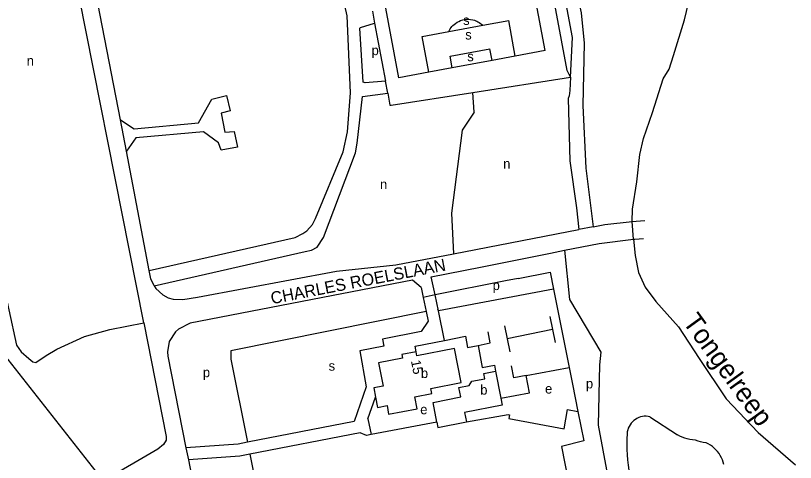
# Model space of a CAD drawing. Extents: x 160204 to 161526, y 379528 to 381793.
# Drawn here: x 160863 to 161185.5, y 379877.4 to 380062.1 of the extents above; entities that cross this region are included whole.
import ezdxf

# ---------------------------------------------------------------- set-up
doc = ezdxf.new("R2010")
doc.units = 0
for name, color, linetype in [('BLT_Basislijn', 7, 'Continuous'), ('BLT_Bebouwing', 7, 'Continuous'), ('BLT_Centroide', 7, 'Continuous'), ('BLT_Huisnummer', 7, 'Continuous'), ('BLT_Straatnaam', 7, 'Continuous'), ('BLT_Vlakafsluiter', 7, 'Continuous'), ('BLT_Waternaam_spoorwegen', 7, 'Continuous')]:
    doc.layers.add(name, color=color, linetype=linetype)

msp = doc.modelspace()

# ---------------------------------------------------------------- linework, layer by layer
at = {"layer": 'BLT_Basislijn'}
for p, q in [((161081.96, 380047.64), (161073.27, 380094.34)), ((161021.52, 380036.39), (161012.83, 380083.09)), ((161010.55, 380063.98), (161011.49, 380058.99)), ((161056.23, 380058.14), (161066.92, 380060.13)), ((161069.67, 380045.35), (161066.92, 380060.13)), ((161011.49, 380058.99), (161015.91, 380035.07)), ((161042.15, 380055.52), (161056.23, 380058.14)), ((161031.12, 380053.47), (161042.15, 380055.52)), ((161033.87, 380038.68), (161031.12, 380053.47)), ((161042.7, 380045.33), (161059.14, 380048.39)), ((161060.04, 380043.56), (161059.14, 380048.39)), ((161081.96, 380047.64), (161069.67, 380045.35)), ((161043.6, 380040.5), (161042.7, 380045.33)), ((161060.04, 380043.56), (161043.6, 380040.5)), ((161069.67, 380045.35), (161060.04, 380043.56)), ((161043.6, 380040.5), (161033.87, 380038.68)), ((161033.87, 380038.68), (161021.52, 380036.39)), ((161052.04, 380030.35), (161092.51, 380036.64)), ((161016.88, 380030), (161015.91, 380035.07)), ((161052.7, 380022.15), (161052.04, 380030.35)), ((161044.12, 379963.67), (161095.92, 379973.72)), ((161101.9, 379974.84), (161095.92, 379973.72)), ((161034.89, 379954.19), (161055.22, 379958.12)), ((161030.74, 379949.66), (161027.14, 379952.69)), ((161036.47, 379946.63), (161034.89, 379954.19)), ((161070.84, 379953.44), (161065.66, 379952.53)), ((161030.74, 379949.66), (161031.55, 379945.64)), ((161065.66, 379952.53), (161036.47, 379946.63)), ((161036.47, 379946.63), (161031.55, 379945.64)), ((161037.84, 379940.05), (161036.47, 379946.63)), ((161085.44, 379949.07), (161037.84, 379940.05)), ((161085.44, 379949.07), (161091.9, 379916.71)), ((161031.55, 379945.64), (161032.73, 379939.83)), ((161037.74, 379940.29), (161037.63, 379940.82)), ((161040.38, 379927.87), (161037.84, 379940.05)), ((161083.99, 379937.76), (161085.1, 379932.37)), ((161065.2, 379933.9), (161066.31, 379928.5)), ((161085.1, 379932.37), (161066.31, 379928.5)), ((161085.1, 379932.37), (161086.21, 379926.98)), ((161066.31, 379928.5), (161067.42, 379923.11)), ((161074.15, 379913.37), (161091.9, 379916.71)), ((161091.9, 379916.71), (161093.29, 379909.74)), ((161093.29, 379909.74), (161095.53, 379898.51)), ((161008.73, 379895.43), (161011.84, 379904.41)), ((161008.73, 379895.43), (161010.08, 379888.93)), ((161049.44, 379894.12), (161066.72, 379897.25)), ((161125.34, 379896.31), (161136.76, 379888.84)), ((161003.06, 379894.32), (160958.9, 379885.77)), ((161037.23, 379894.01), (161010.08, 379888.93)), ((160933.45, 379883.39), (160934.43, 379878.45)), ((160934.43, 379878.45), (160969.28, 379702.73))]:
    msp.add_line(p, q, dxfattribs=at)
for points in [[(160918.29, 379956.68), (160978.67, 379970.4), (160981.76, 379971.99), (160983.39, 379973.19), (160985.73, 379975.8), (160987, 379978.19), (160998.45, 380005.86), (161000.28, 380014.12), (161001.44, 380030.18), (161000.06, 380062.07), (160991.56, 380100), (160982.83, 380140.2), (160929.54, 380218.51), (160925.74, 380224.32)], [(161113.04, 380224.32), (161105.82, 380221.49), (161072.03, 380195.82), (161081.69, 380142.89), (161089.85, 380100), (161094.29, 380075.45), (161096.83, 380063.3), (161098.08, 380050.73), (161097.61, 380024.93), (161098.88, 379999.01), (161101.9, 379974.84)], [(161092.51, 380036.64), (161091.14, 380039.36), (161079.84, 380100), (161068.83, 380159.58)], [(161092.51, 380036.64), (161093.27, 380052.99), (161084.55, 380100), (161073.45, 380160.43)], [(160916.02, 379935.16), (160883.29, 380100), (160882.24, 380105.15)], [(161118.03, 379977.03), (161118.12, 379982.05), (161119.95, 379993.38), (161121.14, 380004.68), (161122.65, 380011.37), (161126.35, 380022.08), (161130.87, 380035.99), (161133.25, 380040), (161135.15, 380045.66), (161139.69, 380060.35), (161145.61, 380085.22), (161148, 380098.65)], [(160906.32, 380018.98), (160894.3, 380081.57)], [(161042.15, 380055.52), (161042.46, 380056.13), (161042.77, 380056.63), (161043.15, 380057.21), (161043.46, 380057.57), (161043.82, 380057.95), (161044.34, 380058.44), (161044.89, 380058.88), (161045.59, 380059.36), (161046.26, 380059.73), (161047.01, 380060.04), (161047.93, 380060.32), (161048.71, 380060.49), (161049.37, 380060.58), (161049.93, 380060.6), (161050.35, 380060.6), (161051.16, 380060.53), (161052.06, 380060.39), (161052.74, 380060.2), (161053.33, 380059.98), (161053.76, 380059.8), (161054.18, 380059.59), (161054.69, 380059.3), (161055.28, 380058.9), (161055.66, 380058.61), (161056.23, 380058.14)], [(161015.91, 380035.07), (161007.63, 380034.26), (161006.77, 380034.55), (161005.42, 380056.93), (161005.64, 380057.22), (161011.49, 380058.99)], [(160836.31, 380050.55), (160847.3, 379998.87), (160863.34, 379925.87), (160865.34, 379923.18), (160868.52, 379920.3), (160870.11, 379919.03), (160871.42, 379918.73), (160875.68, 379921.67), (160880.04, 379924.17), (160891.52, 379929.46), (160901.95, 379932.32), (160916.02, 379935.16)], [(161092.51, 380036.64), (161092.21, 380031.11), (161091.93, 380028.88), (161091.52, 380027.87), (161092.17, 380002.01), (161094.93, 379982.64), (161095.92, 379973.72)], [(161016.88, 380030), (161017.81, 380025.09), (161018.38, 380025.12), (161052.04, 380030.35)], [(160906.32, 380018.98), (160912.03, 380015.26), (160938.66, 380017.79), (160944.14, 380027.63), (160950.21, 380029.03), (160951.7, 380022.7), (160947.95, 380021.8), (160949.47, 380013.87), (160953.44, 380014.26), (160954.75, 380007.73), (160948.01, 380006.42), (160946.86, 380009.58), (160940.66, 380014.01), (160912.77, 380011.64), (160908.79, 380006.13)], [(160920.31, 379950.39), (160982.81, 379964.53), (160985.41, 379965.2), (160987.74, 379966.42), (160990.34, 379970.33), (161003.54, 380005.32), (161004.32, 380009.42), (161006.4, 380028.63), (161016.88, 380030)], [(161052.7, 380022.15), (161047.69, 380014.73), (161043.27, 379980.48), (161044.12, 379963.67)], [(160908.79, 380006.13), (160906.32, 380018.98)], [(160918.29, 379956.68), (160908.79, 380006.13)], [(160899.34, 379869.75), (160838.56, 379946.96), (160831.95, 379953.52), (160783.95, 379999.78)], [(161101.9, 379974.84), (161106.71, 379975.73), (161118.03, 379977.03)], [(161118.03, 379977.03), (161119.71, 379977.18), (161123.19, 379977.44)], [(161089.98, 379965.09), (161104.33, 379967.86), (161118.57, 379969.66)], [(161118.57, 379969.66), (161119.13, 379969.7), (161122.67, 379969.98)], [(161118.57, 379969.66), (161119.2, 379962.98), (161120.6, 379955.98), (161123.32, 379949.89), (161127.74, 379943.91), (161137.09, 379933.46), (161145.64, 379920.34), (161156.9, 379903.73), (161170.11, 379889.75), (161185.51, 379876.4)], [(160920.31, 379950.39), (160920.97, 379949.3), (160923.93, 379946.64), (160926.15, 379945.42), (160928.19, 379944.86), (160932.09, 379944.76), (160938.26, 379945.65), (160995.69, 379956.42), (161020.24, 379959.04), (161044.12, 379963.67)], [(161055.22, 379958.12), (161084.17, 379963.97), (161089.98, 379965.09)], [(161089.98, 379965.09), (161092.01, 379944.76), (161104.98, 379922.95), (161104.46, 379917.75), (161103.95, 379892.82), (161121.59, 379798.29), (161131.97, 379787.9), (161128.34, 379764.01), (161135.09, 379725.05), (161131.8, 379715.9)], [(160920.31, 379950.39), (160918.98, 379953.27), (160918.29, 379956.68)], [(161070.84, 379953.44), (161084.06, 379955.99), (161085.44, 379949.07)], [(161027.14, 379952.69), (160935.22, 379934.92), (160930.39, 379932.55), (160929.12, 379931.43), (160926.53, 379927.45), (160925.78, 379923.07), (160925.93, 379921.32), (160933.45, 379883.39)], [(161032.73, 379939.83), (160951.95, 379923.58), (160952.05, 379920.1), (160958.9, 379885.77)], [(161032.73, 379939.83), (161033.56, 379935.78), (161030.74, 379931.55), (161014.74, 379928.36), (161015.31, 379925.53), (161005.32, 379923.52), (161008.01, 379908.64), (161003.06, 379894.32)], [(160916.02, 379935.16), (160925.3, 379888.11), (160925.28, 379886.57), (160924.22, 379884.76), (160921.8, 379882.93), (160899.34, 379869.75)], [(161054.27, 379925.8), (161059.28, 379926.78), (161058.39, 379931.38)], [(161028.64, 379923.16), (161028.18, 379925.45), (161040.38, 379927.87)], [(161040.38, 379927.87), (161049.02, 379929.59), (161049.9, 379924.96), (161054.27, 379925.8)], [(161054.27, 379925.8), (161056.02, 379916.68), (161061.02, 379917.6), (161061.52, 379915.17)], [(161074.15, 379913.37), (161069.08, 379912.41), (161068.15, 379917.36)], [(161063.72, 379903.92), (161075.47, 379906.16), (161074.15, 379913.37)], [(161066.72, 379897.25), (161067.3, 379897.14), (161067.02, 379895.57), (161089.8, 379891.24), (161091.18, 379899.26), (161095.53, 379898.51)], [(161095.53, 379898.51), (161097.96, 379886.33), (161088.72, 379883.92), (161122.15, 379713.93)], [(161125.34, 379896.31), (161124.56, 379896.45), (161123.78, 379896.51), (161122.99, 379896.49), (161122.21, 379896.38), (161121.45, 379896.2), (161120.71, 379895.95), (161119.99, 379895.61), (161119.32, 379895.21), (161118.69, 379894.74), (161118.11, 379894.22), (161117.58, 379893.63), (161117.12, 379892.99), (161116.73, 379892.31), (161116.4, 379891.6), (161116.16, 379890.85), (161115.99, 379890.08), (161115.89, 379889.28)], [(161010.08, 379888.93), (161008.06, 379888.49), (161005.5, 379889.69), (160959.88, 379880.87)], [(161115.89, 379889.28), (161115.77, 379887.11), (161115.72, 379884.95), (161115.75, 379882.78), (161115.87, 379880.61), (161116.06, 379878.46), (161116.33, 379876.3), (161116.68, 379874.17), (161117.12, 379872.04), (161117.62, 379869.93), (161118.21, 379867.85), (161118.31, 379867.53)], [(161144, 379886.64), (161142.92, 379886.72), (161141.83, 379886.88), (161140.77, 379887.12), (161139.72, 379887.44), (161138.7, 379887.83), (161137.71, 379888.3), (161136.76, 379888.84)], [(160958.9, 379885.77), (160955.02, 379885.02), (160933.45, 379883.39)], [(161148.4, 379885.54), (161147.33, 379885.68), (161146.27, 379885.89), (161145.24, 379886.18), (161144.23, 379886.55), (161144, 379886.64)], [(161155.86, 379876.53), (161155.62, 379877.5), (161155.3, 379878.45), (161154.91, 379879.37), (161154.44, 379880.26), (161153.91, 379881.1), (161153.31, 379881.9), (161152.64, 379882.65), (161151.92, 379883.34), (161151.15, 379883.97), (161150.33, 379884.54), (161149.46, 379885.04), (161148.56, 379885.48), (161148.4, 379885.54)], [(160959.88, 379880.87), (160955.68, 379880.06), (160934.43, 379878.45)], [(160959.88, 379880.87), (160983.6, 379762), (161001.22, 379671.83), (161001.95, 379671.12), (161047.14, 379679.9)]]:
    msp.add_lwpolyline(points, dxfattribs=at)
at = {"layer": 'BLT_Bebouwing'}
for p, q in [((161061.52, 379915.17), (161063.72, 379903.92)), ((161011.09, 379908.23), (161011.84, 379904.41))]:
    msp.add_line(p, q, dxfattribs=at)
for points in [[(161028.11, 379904.52), (161035.16, 379905.9), (161034.76, 379907.96), (161047.27, 379910.4), (161044.51, 379924.54)], [(161044.51, 379924.54), (161028.96, 379921.51), (161028.64, 379923.16)], [(161028.64, 379923.16), (161022.77, 379922.01), (161023.05, 379920.54), (161013.14, 379918.61)], [(161013.14, 379918.61), (161015.02, 379908.99), (161011.09, 379908.23)], [(161046.36, 379908.36), (161050.56, 379909.21), (161051.74, 379910.97), (161057.06, 379912.01), (161056.63, 379914.22), (161061.52, 379915.17)], [(161037.23, 379894.01), (161035.63, 379902.24), (161047.12, 379904.47), (161046.36, 379908.36)], [(161011.84, 379904.41), (161012.68, 379900.11), (161016.6, 379900.87), (161017.23, 379897.34), (161029.03, 379899.62), (161028.11, 379904.52)], [(161063.72, 379903.92), (161064.27, 379901.09), (161048.67, 379898.05), (161049.44, 379894.12)], [(161037.23, 379894.01), (161037.66, 379891.83), (161049.44, 379894.12)]]:
    msp.add_lwpolyline(points, dxfattribs=at)
at = {"layer": 'BLT_Vlakafsluiter'}
msp.add_line((161118.57, 379969.66), (161118.03, 379977.03), dxfattribs=at)

# ---------------------------------------------------------------- texts
at = {"layer": 'BLT_Centroide'}
for s, p in [('s', (161048.09, 380058.23)), ('s', (161048.94, 380052.23)), ('p', (161010.23, 380045.75)), ('s', (161049.8, 380043.24)), ('n', (160867.6, 380041.46)), ('n', (161064.65, 379998.9)), ('n', (161013.69, 379990.4)), ('p', (161060.29, 379948.65)), ('s', (160992.45, 379915.32)), ('p', (160940.43, 379912.65)), ('b', (161030.62, 379912.31)), ('p', (161098.88, 379908)), ('b', (161055.16, 379905.44)), ('e', (161081.97, 379905.88)), ('e', (161030.34, 379897.31))]:
    msp.add_text(s, height=4, dxfattribs=at).set_placement(p)
at = {"layer": 'BLT_Huisnummer'}
msp.add_text('15', height=4, rotation=281.0359, dxfattribs=at).set_placement((161026.48, 379919.36))
at = {"layer": 'BLT_Straatnaam'}
msp.add_text('CHARLES ROELSLAAN', height=5, rotation=10.9748, dxfattribs=at).set_placement((160969, 379942.78))
at = {"layer": 'BLT_Waternaam_spoorwegen'}
msp.add_text('Tongelreep', height=8, rotation=305.8858, dxfattribs=at).set_placement((161138.64, 379935.44))

doc.saveas('drawing.dxf')
